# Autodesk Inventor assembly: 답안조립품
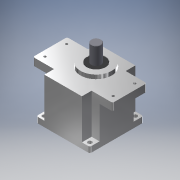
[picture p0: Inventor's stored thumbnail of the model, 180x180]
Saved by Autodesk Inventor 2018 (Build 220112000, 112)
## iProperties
Created: 2020-07
Part Number: 답안조립품
Material: 일반
Document SubType Name: Assembly
Designer: admin
Author: admin
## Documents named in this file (10)
- C:\Users\admin\Desktop\700707V1004\답안조립품.iam
- C:\Users\admin\Desktop\700707V1004\본체.ipt
- C:\Users\admin\Desktop\700707V1004\커버.ipt
- C:\Users\admin\Desktop\700707V1004\메인 축.ipt
- C:\Users\admin\Desktop\700707V1004\서브 축.ipt
- C:\Users\admin\Desktop\700707V1004\베어링 608.ipt
- C:\Users\admin\Desktop\700707V1004\베어링 6003.ipt
- C:\Users\admin\Desktop\700707V1004\볼트 M4.ipt
- C:\Users\admin\Desktop\700707V1004\오일 실 8 22 7.ipt
- C:\Users\admin\Desktop\700707V1004\오일 실 17 32 8.ipt
